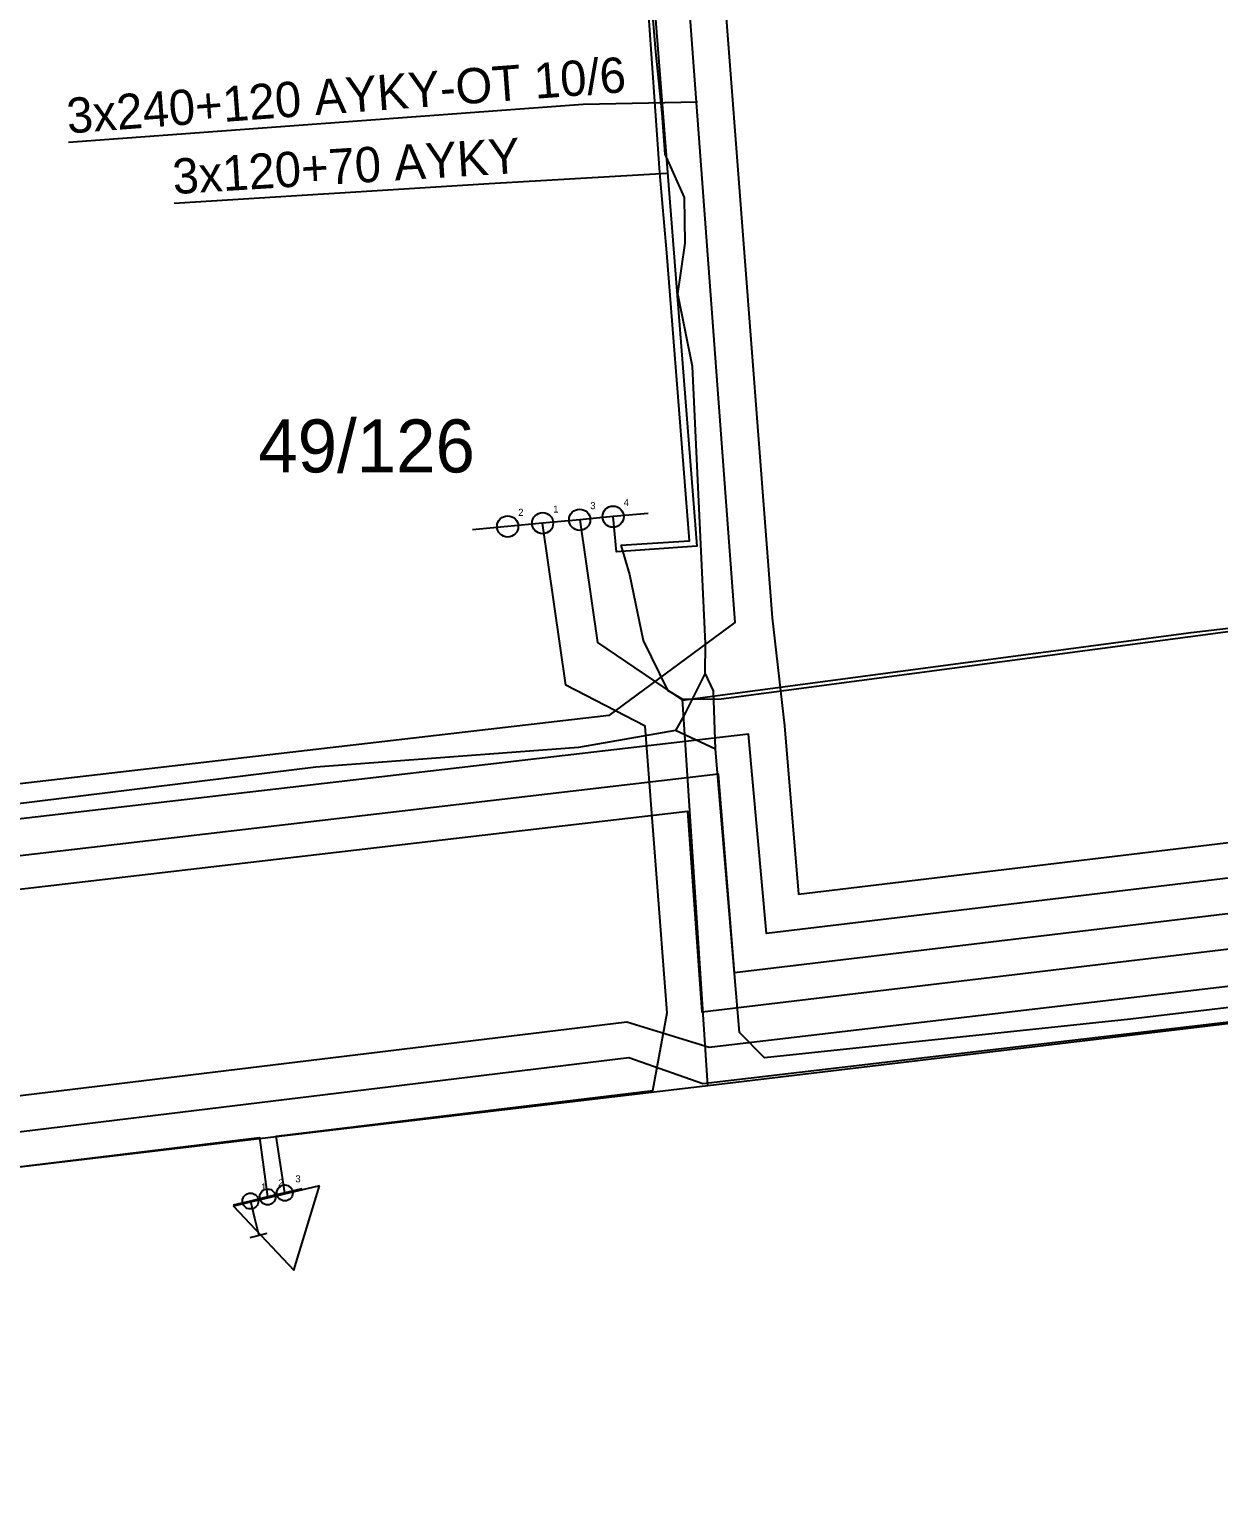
# Model space of a CAD drawing. Extents: x -744800 to -744528, y -1052473 to -1052336.
# Drawn here: x -744644.94 to -744611.28, y -1052412.58 to -1052370.65 of the extents above; entities that cross this region are included whole.
import ezdxf

# ---------------------------------------------------------------- set-up
doc = ezdxf.new("R2010")
doc.units = 0
for name, color, linetype in [('NN_CISLO_VYVODU', 7, 'Continuous'), ('NN_CISLO_VYVODU_SP', 7, 'Continuous'), ('NN_KABEL_INSTALACE_SP_PROVOZ', 7, 'Continuous'), ('NN_KABELOVE_VEDENI_PROVOZ', 7, 'Continuous'), ('NN_POPIS_USEKU', 7, 'Continuous'), ('NN_PRIPOJKOVA_SKRIN', 7, 'Continuous'), ('NN_PRIPOJNICE_RIS', 7, 'Continuous'), ('NN_PRIPOJNICE_SP', 7, 'Continuous'), ('NN_PRIPOJOVACI_MISTO', 7, 'Continuous'), ('NN_RIS', 7, 'Continuous'), ('NN_VYVODY', 7, 'Continuous'), ('NN_VYVODY_SP', 7, 'Continuous'), ('TRASA_KABELU_NN_PROVOZ', 7, 'Continuous')]:
    doc.layers.add(name, color=color, linetype=linetype)

msp = doc.modelspace()

# ---------------------------------------------------------------- linework, layer by layer
at = {"layer": 'NN_KABEL_INSTALACE_SP_PROVOZ'}
msp.add_line((-744638.686, -1052403.819), (-744638.571, -1052404.306), dxfattribs=at)
at = {"layer": 'NN_KABELOVE_VEDENI_PROVOZ'}
for points in [[(-744633.183, -1052356.642), (-744633.521, -1052351.56), (-744626.684, -1052351.094), (-744623.911, -1052387.31), (-744623.568, -1052390.367), (-744623.165, -1052395.131), (-744564.248, -1052388.055), (-744552.516, -1052404.718), (-744538.787, -1052394.869), (-744542.655, -1052389.688), (-744543.251, -1052380.647), (-744543.648, -1052379.434), (-744543.791, -1052377.578), (-744544.659, -1052368.082), (-744547.073, -1052354.821), (-744543.518, -1052347.643), (-744535.387, -1052345.83), (-744534.333, -1052350.257)], [(-744535.725, -1052350.166), (-744536.539, -1052347.029), (-744542.833, -1052348.513), (-744546.03, -1052354.968), (-744543.667, -1052367.947), (-744542.794, -1052377.494), (-744542.66, -1052379.237), (-744542.264, -1052380.448), (-744541.729, -1052389.291), (-744537.38, -1052395.122), (-744556.054, -1052408.356), (-744556.636, -1052407.541), (-744553.323, -1052405.266), (-744564.717, -1052389.127), (-744624.074, -1052396.246), (-744624.583, -1052390.597), (-744662.551, -1052395.016)], [(-744537.048, -1052350.359), (-744537.561, -1052348.275), (-744542.149, -1052349.383), (-744544.986, -1052355.114), (-744542.689, -1052367.739), (-744541.797, -1052377.417), (-744541.672, -1052379.041), (-744541.277, -1052380.249), (-744540.75, -1052388.947), (-744535.972, -1052395.375), (-744556.265, -1052409.748), (-744558.027, -1052407.303), (-744554.757, -1052405.017), (-744565.186, -1052390.199), (-744624.983, -1052397.36), (-744625.43, -1052391.735), (-744663.451, -1052396.18)], [(-744538.381, -1052350.871), (-744538.795, -1052349.559), (-744541.464, -1052350.254), (-744543.943, -1052355.261), (-744541.71, -1052367.53), (-744540.8, -1052377.34), (-744540.684, -1052378.844), (-744540.29, -1052380.05), (-744539.771, -1052388.576), (-744534.484, -1052395.587), (-744556.551, -1052411.113), (-744559.424, -1052407.065), (-744556.106, -1052404.763), (-744565.654, -1052391.273), (-744625.892, -1052398.475), (-744626.303, -1052392.793), (-744664.403, -1052397.238)], [(-744632.192, -1052356.508), (-744632.59, -1052352.533), (-744627.595, -1052352.131), (-744624.97, -1052387.437), (-744628.541, -1052390.068), (-744661.572, -1052393.905), (-744661.969, -1052380.543), (-744664.088, -1052353.097), (-744690.819, -1052354.788), (-744690.316, -1052362.699), (-744697.407, -1052363.175), (-744697.161, -1052368.506), (-744701.87, -1052368.837)], [(-744631.201, -1052356.374), (-744631.51, -1052353.316), (-744628.568, -1052353.147), (-744626.044, -1052385.278), (-744628.324, -1052385.438), (-744628.417, -1052384.441)], [(-744799.958, -1052408.482), (-744800.116, -1052406.505), (-744794.132, -1052405.926), (-744768.563, -1052404.243), (-744751.319, -1052402.793), (-744733.275, -1052401.051), (-744733.48, -1052398.511), (-744731.401, -1052398.392), (-744727.771, -1052398.622), (-744714.274, -1052400.592), (-744713.445, -1052400.003), (-744705.181, -1052400.423), (-744705.583, -1052403.661), (-744687.509, -1052405.817), (-744668.651, -1052404.712), (-744627.976, -1052399.751), (-744625.876, -1052400.487), (-744566.945, -1052393.578), (-744568.26, -1052383.974), (-744549.76, -1052382.661), (-744547.856, -1052381.455), (-744527.683, -1052380.355), (-744528.085, -1052374.982), (-744530.485, -1052375.105)], [(-744701.233, -1052459.94), (-744697.975, -1052462.013), (-744701.204, -1052455.312), (-744721.631, -1052413.856), (-744727.534, -1052401.666), (-744727.626, -1052397.603), (-744714.621, -1052399.45), (-744713.238, -1052398.803), (-744704.151, -1052399.748), (-744704.544, -1052402.838), (-744687.321, -1052404.806), (-744668.44, -1052403.653), (-744628.032, -1052398.743), (-744625.696, -1052399.462), (-744568.109, -1052392.689), (-744569.387, -1052383.09), (-744550.152, -1052381.714), (-744547.961, -1052380.354), (-744528.632, -1052379.391), (-744528.92, -1052376.499)], [(-744629.363, -1052384.529), (-744628.863, -1052388.006), (-744626.453, -1052389.637), (-744612.048, -1052387.723), (-744598.426, -1052386.136), (-744595.364, -1052385.498), (-744586.706, -1052384.269), (-744589.152, -1052380.934), (-744588.911, -1052380.757), (-744589.21, -1052378.482)], [(-744637.713, -1052403.59), (-744637.96, -1052401.981), (-744627.292, -1052400.69), (-744626.889, -1052398.489), (-744627.508, -1052390.377), (-744629.752, -1052389.212), (-744630.413, -1052384.626)], [(-744655.573, -1052406.056), (-744655.676, -1052404.119), (-744638.425, -1052402.024), (-744638.199, -1052403.704)]]:
    msp.add_lwpolyline(points, dxfattribs=at)
at = {"layer": 'NN_POPIS_USEKU'}
for points in [[(-744643.834, -1052373.842), (-744629.265, -1052372.759), (-744626.027, -1052372.695)], [(-744640.846, -1052375.56), (-744631.927, -1052375.012), (-744626.894, -1052374.719)]]:
    msp.add_lwpolyline(points, dxfattribs=at)
at = {"layer": 'NN_PRIPOJKOVA_SKRIN'}
msp.add_lwpolyline([(-744636.734, -1052403.387), (-744639.167, -1052403.962), (-744637.452, -1052405.781)], close=True, dxfattribs=at)
at = {"layer": 'NN_PRIPOJNICE_RIS'}
msp.add_lwpolyline([(-744627.42, -1052384.348), (-744628.417, -1052384.441), (-744629.363, -1052384.529), (-744630.413, -1052384.626), (-744631.403, -1052384.718), (-744632.399, -1052384.811)], dxfattribs=at)
at = {"layer": 'NN_PRIPOJNICE_SP'}
msp.add_lwpolyline([(-744637.226, -1052403.475), (-744637.713, -1052403.59), (-744638.199, -1052403.704), (-744638.686, -1052403.819), (-744639.173, -1052403.934)], dxfattribs=at)
at = {"layer": 'NN_PRIPOJOVACI_MISTO'}
for p, q in [((-744638.571, -1052404.306), (-744638.45, -1052404.791)), ((-744638.693, -1052404.852), (-744638.207, -1052404.731))]:
    msp.add_line(p, q, dxfattribs=at)
at = {"layer": 'NN_VYVODY'}
for centre in [(-744631.403, -1052384.718), (-744630.413, -1052384.626), (-744629.363, -1052384.529), (-744628.417, -1052384.441)]:
    msp.add_circle(centre, 0.3, dxfattribs=at)
at = {"layer": 'NN_VYVODY_SP'}
for centre in [(-744638.686, -1052403.819), (-744638.199, -1052403.704), (-744637.713, -1052403.59)]:
    msp.add_circle(centre, 0.225, dxfattribs=at)
at = {"layer": 'TRASA_KABELU_NN_PROVOZ'}
for p, q in [((-744625.739, -1052400.545), (-744626.45, -1052389.612)), ((-744625.52, -1052391.02), (-744626.65, -1052390.5))]:
    msp.add_line(p, q, dxfattribs=at)
for points in [[(-744628.2, -1052385.252), (-744626.254, -1052385.13), (-744626.9, -1052376.968), (-744627.09, -1052374.703), (-744627.788, -1052364.727), (-744628.177, -1052359.852), (-744628.642, -1052352.639)], [(-744625.81, -1052388.87), (-744625.8, -1052388.03), (-744626.17, -1052380.19), (-744626.58, -1052378.13), (-744626.38, -1052376.7), (-744626.4, -1052375.4), (-744626.94, -1052374.18), (-744627.03, -1052373.02), (-744627.21, -1052371.28), (-744627.78, -1052364.34), (-744628.64, -1052353.92), (-744629.34, -1052353.53), (-744631.43, -1052353.68), (-744632.06, -1052354.18)], [(-744626.65, -1052390.5), (-744629.4, -1052390.98), (-744636.83, -1052391.53), (-744649.33, -1052393.07), (-744662.48, -1052394.46), (-744663.54, -1052393.95), (-744663.69, -1052389.23), (-744663.86, -1052383.07), (-744664, -1052379.52), (-744664.68, -1052371.75), (-744665.64, -1052359.18), (-744666.23, -1052358.41), (-744667.61, -1052358.28), (-744669.96, -1052358.61), (-744684.55, -1052359.69), (-744685.88, -1052360.35), (-744687.95, -1052362.53), (-744689.06, -1052364.05), (-744693.94, -1052364.63), (-744697.19, -1052364.76)], [(-744626.423, -1052389.611), (-744625.36, -1052389.602), (-744602.84, -1052386.612), (-744598.3, -1052386.162), (-744593.46, -1052385.162), (-744586.32, -1052384.2)], [(-744628.2, -1052385.252), (-744627.95, -1052386.082), (-744627.57, -1052387.952), (-744626.88, -1052389.352), (-744626.45, -1052389.612), (-744626.423, -1052389.611)], [(-744625.81, -1052388.87), (-744626.4, -1052390.04), (-744626.65, -1052390.5)], [(-744625.52, -1052391.02), (-744625.57, -1052389.37), (-744625.81, -1052388.87)], [(-744570.78, -1052393.81), (-744578.31, -1052394.55), (-744581.85, -1052395.1), (-744597.35, -1052396.73), (-744613.77, -1052398.67), (-744624.13, -1052399.76), (-744624.84, -1052399.05), (-744625.52, -1052391.02)], [(-744625.739, -1052400.545), (-744593.305, -1052396.676), (-744566.393, -1052393.669)], [(-744707.06, -1052404.212), (-744705.621, -1052404.634), (-744687.963, -1052406.758), (-744687.133, -1052406.691), (-744684.137, -1052406.542), (-744680.842, -1052406.363), (-744668.909, -1052405.665), (-744645.458, -1052402.883), (-744625.739, -1052400.545)]]:
    msp.add_lwpolyline(points, dxfattribs=at)

# ---------------------------------------------------------------- texts
at = {"layer": 'NN_CISLO_VYVODU'}
for s, p in [('3', (-744629.063, -1052384.229)), ('4', (-744628.117, -1052384.141)), ('2', (-744631.103, -1052384.418)), ('1', (-744630.113, -1052384.326))]:
    msp.add_text(s, height=0.2, dxfattribs=at).set_placement(p)
at = {"layer": 'NN_CISLO_VYVODU_SP'}
for s, p in [('1', (-744638.386, -1052403.519)), ('2', (-744637.899, -1052403.404)), ('3', (-744637.413, -1052403.29))]:
    msp.add_text(s, height=0.2, dxfattribs=at).set_placement(p)
at = {"layer": 'NN_POPIS_USEKU'}
for s, rotation, p in [('3x240+120 AYKY-OT 10/6', 4.2516, (-744643.852, -1052373.593)), ('3x120+70 AYKY', 3.5114, (-744640.861, -1052375.31))]:
    msp.add_text(s, height=1, rotation=rotation, dxfattribs=at).set_placement(p)
at = {"layer": 'NN_RIS'}
msp.add_text('49/126', height=1.5, dxfattribs=at).set_placement((-744638.464, -1052383.189))

doc.saveas('drawing.dxf')
